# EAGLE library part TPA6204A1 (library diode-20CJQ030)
Ti's TPA6204A1 1.7-W mono fully-differential audio amplifier DESCRIPTION The TPA6204A1 is a 1.7-W mono fully-differential amplifier designed to drive a speaker with at least 8-? impedance while consuming only 20 mm2 total printed-circuit board (PCB) area in most applications. The device operates from 2.5 V to 5.5 V, drawing only 4 mA of quiescent supply current. The TPA6204A1 is available in the space-saving 3 mm x 3 mm QFN (DRB) package. The TPA6204A1 is ideal for PDA/smart phone applications due to features such as ?80-dB supply voltage rejection from 20 Hz to 2 kHz, improved RF rectification immunity, small PCB area, and a fast startup with minimal pop. FEATURES Designed for Wireless or Cellular Handsets and PDAs 1.7 W Into 8 ? From a 5-V Supply at THD = 10% (Typ) Low Supply Current: 4 mA typ at 5 V Shutdown Current: 0.01 uA Typ Fast Startup With Minimal Pop Only Three External Components - Improved PSRR (?80 dB) and Wide Supply Voltage (2.5 V to 5.5 V) for Direct Battery Operation - Fully Differential Design Reduces RF Rectification - -63 dB CMRR Eliminates Two Input Coupling Capacitors Pin to Pin Compatible With TPA2005D1 and TPA6211A1 in QFN Package Available in 3 mm X 3 mm QFN Package (DRB) APPLICATIONS Ideal for Wireless Handsets PDAs Notebook Computers Please send any comments to: messi@users.sourceforge.net
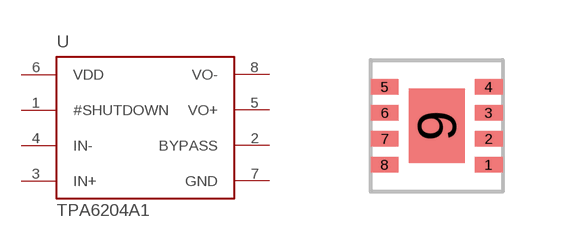
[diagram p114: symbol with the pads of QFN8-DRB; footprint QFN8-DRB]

Designator prefix U

## TPA6204A1-DRB  [QFN8-DRB]
1  #SHUTDOWN  in
2  BYPASS  pas
3  IN+  in
4  IN-  in
5  VO+  out
6  VDD  pwr
7  GND  pwr
8  VO-  out

## Footprint QFN8-DRB (pad centres in mm)
smd 0.7 x 0.38: 1 1.3,-0.975; 2 1.3,-0.325; 3 1.3,0.325; 4 1.3,0.975; 5 -1.3,0.975; 6 -1.3,0.325; 7 -1.3,-0.325; 8 -1.3,-0.975
smd 1.4 x 1.85: 9 0,0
